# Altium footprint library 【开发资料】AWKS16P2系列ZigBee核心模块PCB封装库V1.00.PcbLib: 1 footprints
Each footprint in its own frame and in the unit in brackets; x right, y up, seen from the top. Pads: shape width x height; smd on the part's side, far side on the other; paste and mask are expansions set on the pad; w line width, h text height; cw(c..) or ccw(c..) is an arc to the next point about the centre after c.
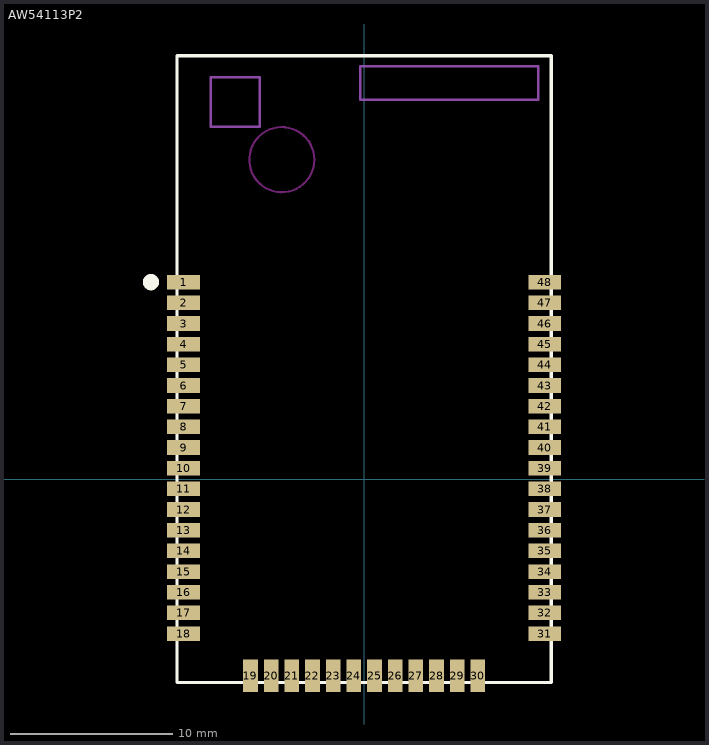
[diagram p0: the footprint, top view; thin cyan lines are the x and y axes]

## AW54113P2 [mm] "1.14.21.0244 171116 Rev.B"
pads (48):
  rect 2x0.9 smd mask+0.051: 1(-11.1,12.095) 2(-11.1,10.825) 3(-11.1,9.555) 4(-11.1,8.285) 5(-11.1,7.015) 6(-11.1,5.745) 7(-11.1,4.475) 8(-11.1,3.205) 9(-11.1,1.935) 10(-11.1,0.665) 11(-11.1,-0.605) 12(-11.1,-1.875) 13(-11.1,-3.145) 14(-11.1,-4.415) 15(-11.1,-5.685) 16(-11.1,-6.955) 17(-11.1,-8.225) 18(-11.1,-9.495) 31(11.1,-9.495) 32(11.1,-8.225) 33(11.1,-6.955) 34(11.1,-5.685) 35(11.1,-4.415) 36(11.1,-3.145) 37(11.1,-1.875) 38(11.1,-0.605) 39(11.1,0.665) 40(11.1,1.935) 41(11.1,3.205) 42(11.1,4.475) 43(11.1,5.745) 44(11.1,7.015) 45(11.1,8.285) 46(11.1,9.555) 47(11.1,10.825) 48(11.1,12.095)
  rect 0.9x2 smd mask+0.051: 19(-6.985,-12.095) 20(-5.715,-12.095) 21(-4.445,-12.095) 22(-3.175,-12.095) 23(-1.905,-12.095) 24(-0.635,-12.095) 25(0.635,-12.095) 26(1.905,-12.095) 27(3.175,-12.095) 28(4.445,-12.095) 29(5.715,-12.095) 30(6.985,-12.095)
Top Overlay:
  circle w0.5: c-13.1,12.1 r0.25
  lines w0.2: -11.5,-12.5 11.5,-12.5 ; -11.5,-12.495 -11.5,26.005 11.5,26.005 11.5,-12.495
Keep-Out Layer:
  circle w0.127: c-5.061,19.623 r2
Mechanical 15:
  lines w0.152: -9.432,21.66 -9.432,24.687 -6.405,24.687 -6.405,21.66 -9.432,21.66 ; -0.235,23.294 10.687,23.294 10.687,25.358 -0.235,25.358 -0.235,23.294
